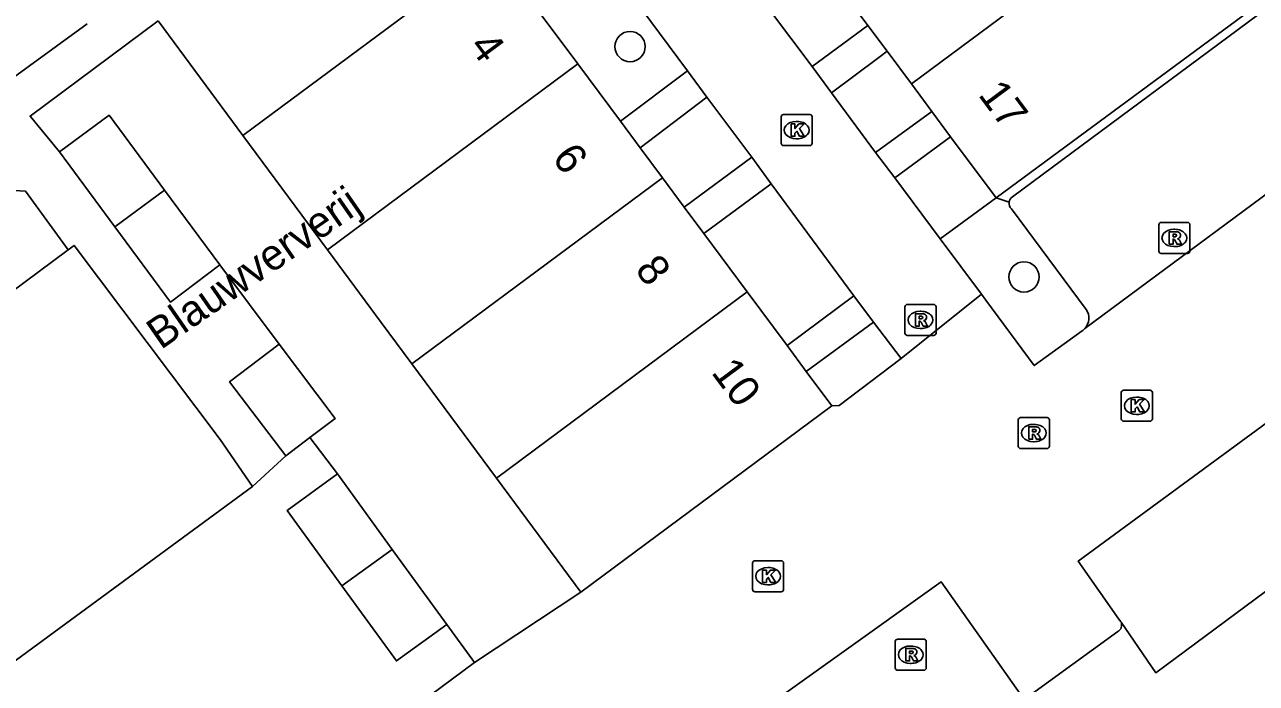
# Model space of a CAD drawing. Extents: x 161801 to 162379, y 382315 to 382832.
# Drawn here: x 162031.71 to 162071.44, y 382446.1 to 382467.36 of the extents above; entities that cross this region are included whole.
import ezdxf

# ---------------------------------------------------------------- set-up
doc = ezdxf.new("R2010")
doc.units = 0
for name, color, linetype in [('IMGEO_Boom', 7, 'Continuous'), ('IMGEO_Erf', 7, 'Continuous'), ('IMGEO_Groenvoorziening', 7, 'Continuous'), ('IMGEO_Kolk', 7, 'Continuous'), ('IMGEO_Openbare_ruimte_label', 7, 'Continuous'), ('IMGEO_Pand', 7, 'Continuous'), ('IMGEO_Pand_nummerreeks', 7, 'Continuous'), ('IMGEO_Parkeervlak_halfverhard', 7, 'Continuous'), ('IMGEO_Parkeervlak_open', 7, 'Continuous'), ('IMGEO_Rijbaan_lokaal_open', 7, 'Continuous'), ('IMGEO_Rioolput', 7, 'Continuous'), ('IMGEO_Voetpad_open', 7, 'Continuous')]:
    doc.layers.add(name, color=color, linetype=linetype)

msp = doc.modelspace()

# ---------------------------------------------------------------- linework, layer by layer
at = {"layer": 'IMGEO_Boom'}
for centre in [(162051.24, 382466.65), (162063.944, 382459.218)]:
    msp.add_circle(centre, 0.489, dxfattribs=at)
at = {"layer": 'IMGEO_Erf'}
for points in [[(162040.915, 382454.037), (162041.8, 382452.86)], [(162045.33, 382447.999), (162046.218, 382446.777)]]:
    msp.add_lwpolyline(points, dxfattribs=at)
at = {"layer": 'IMGEO_Groenvoorziening'}
for points in [[(162063.042, 382461.773), (162061.246, 382460.443)], [(162063.042, 382461.773), (162063.468, 382461.63)]]:
    msp.add_lwpolyline(points, dxfattribs=at)
at = {"layer": 'IMGEO_Kolk'}
for p, q in [((162056.187, 382464.456), (162057.039, 382464.456)), ((162056.112, 382463.53), (162056.112, 382464.382)), ((162056.6, 382464.236), (162056.625, 382464.236)), ((162057.113, 382464.382), (162057.113, 382463.53)), ((162056.623, 382463.676), (162056.598, 382463.676)), ((162057.039, 382463.456), (162056.187, 382463.456)), ((162067.083, 382454.636), (162067.083, 382455.488)), ((162067.158, 382455.562), (162068.01, 382455.562)), ((162067.571, 382455.342), (162067.596, 382455.342)), ((162068.084, 382455.488), (162068.084, 382454.636)), ((162068.01, 382454.562), (162067.158, 382454.562)), ((162067.594, 382454.782), (162067.569, 382454.782)), ((162055.191, 382449.136), (162055.191, 382449.988)), ((162055.266, 382450.062), (162056.118, 382450.062)), ((162055.679, 382449.842), (162055.704, 382449.842)), ((162056.192, 382449.988), (162056.192, 382449.136)), ((162056.118, 382449.062), (162055.266, 382449.062)), ((162055.702, 382449.282), (162055.677, 382449.282))]:
    msp.add_line(p, q, dxfattribs=at)
for points in [[(162056.187, 382464.456), (162057.039, 382464.456)], [(162056.112, 382463.53), (162056.112, 382464.382)], [(162056.433, 382464.156), (162056.556, 382464.156), (162056.556, 382464.005), (162056.686, 382464.156), (162056.85, 382464.156), (162056.704, 382464.005), (162056.857, 382463.756), (162056.705, 382463.756), (162056.62, 382463.92), (162056.556, 382463.853), (162056.556, 382463.756), (162056.433, 382463.756), (162056.433, 382464.156)], [(162057.113, 382464.382), (162057.113, 382463.53)], [(162057.039, 382463.456), (162056.187, 382463.456)], [(162067.083, 382454.636), (162067.083, 382455.488)], [(162067.158, 382455.562), (162068.01, 382455.562)], [(162068.084, 382455.488), (162068.084, 382454.636)], [(162067.404, 382455.262), (162067.527, 382455.262), (162067.527, 382455.111), (162067.657, 382455.262), (162067.821, 382455.262), (162067.675, 382455.111), (162067.828, 382454.862), (162067.676, 382454.862), (162067.591, 382455.026), (162067.527, 382454.959), (162067.527, 382454.862), (162067.404, 382454.862), (162067.404, 382455.262)], [(162068.01, 382454.562), (162067.158, 382454.562)], [(162055.191, 382449.136), (162055.191, 382449.988)], [(162055.266, 382450.062), (162056.118, 382450.062)], [(162055.512, 382449.762), (162055.635, 382449.762), (162055.635, 382449.611), (162055.765, 382449.762), (162055.929, 382449.762), (162055.783, 382449.611), (162055.936, 382449.362), (162055.784, 382449.362), (162055.699, 382449.526), (162055.635, 382449.459), (162055.635, 382449.362), (162055.512, 382449.362), (162055.512, 382449.762)], [(162056.192, 382449.988), (162056.192, 382449.136)], [(162056.118, 382449.062), (162055.266, 382449.062)]]:
    msp.add_lwpolyline(points, dxfattribs=at)
for centre, start, end in [((162056.189, 382464.38), 91.552, 178.448), ((162056.189, 382464.38), 91.552, 178.448), ((162057.037, 382464.38), 1.552, 88.448), ((162057.037, 382464.38), 1.552, 88.448), ((162056.189, 382463.532), 181.552, 268.448), ((162056.189, 382463.532), 181.552, 268.448), ((162057.037, 382463.532), 271.552, 358.448), ((162057.037, 382463.532), 271.552, 358.448), ((162067.16, 382455.486), 91.552, 178.448), ((162067.16, 382455.486), 91.552, 178.448), ((162068.008, 382455.486), 1.552, 88.448), ((162068.008, 382455.486), 1.552, 88.448), ((162067.16, 382454.638), 181.552, 268.448), ((162067.16, 382454.638), 181.552, 268.448), ((162068.008, 382454.638), 271.552, 358.448), ((162068.008, 382454.638), 271.552, 358.448), ((162055.268, 382449.986), 91.552, 178.448), ((162055.268, 382449.986), 91.552, 178.448), ((162056.116, 382449.986), 1.552, 88.448), ((162056.116, 382449.986), 1.552, 88.448), ((162055.268, 382449.138), 181.552, 268.448), ((162055.268, 382449.138), 181.552, 268.448), ((162056.116, 382449.138), 271.552, 358.448), ((162056.116, 382449.138), 271.552, 358.448)]:
    msp.add_arc(centre, 0.0765, start, end, dxfattribs=at)
for centre, major_axis, ratio, start_param, end_param in [((162056.599, 382463.956), (-0.387, 0.002), 0.722429, 4.712389, 7.853982), ((162056.624, 382463.956), (-0.39, 0.002), 0.717154, 1.570796, 4.712389), ((162067.57, 382455.062), (-0.387, 0.002), 0.722429, 4.712389, 7.853982), ((162067.595, 382455.062), (-0.39, 0.002), 0.717154, 1.570796, 4.712389), ((162055.678, 382449.562), (-0.387, 0.002), 0.722429, 4.712389, 7.853982), ((162055.703, 382449.562), (-0.39, 0.002), 0.717154, 1.570796, 4.712389)]:
    msp.add_ellipse(centre, major_axis=major_axis, ratio=ratio, start_param=start_param, end_param=end_param, dxfattribs=at)
at = {"layer": 'IMGEO_Pand'}
for points in [[(162068.51, 382471.53), (162060.316, 382465.444)], [(162068.51, 382471.53), (162071.252, 382467.829), (162063.042, 382461.773)], [(162038.752, 382463.783), (162046.817, 382469.774)], [(162058.911, 382467.335), (162057.589, 382469.115)], [(162048.277, 382467.808), (162049.55, 382466.094)], [(162038.752, 382463.783), (162036.02, 382467.479)], [(162059.529, 382466.503), (162058.911, 382467.335)], [(162060.316, 382465.444), (162059.529, 382466.503)], [(162041.477, 382460.097), (162049.55, 382466.094)], [(162049.55, 382466.094), (162050.926, 382464.243)], [(162060.972, 382464.56), (162060.316, 382465.444)], [(162032.833, 382463.25), (162034.439, 382464.437), (162036.226, 382462.021)], [(162061.579, 382463.743), (162060.972, 382464.56)], [(162050.926, 382464.243), (162051.568, 382463.379)], [(162041.477, 382460.097), (162038.752, 382463.783)], [(162061.579, 382463.743), (162063.042, 382461.773)], [(162032.833, 382463.25), (162034.62, 382460.833)], [(162051.568, 382463.379), (162052.284, 382462.415)], [(162034.62, 382460.833), (162036.226, 382462.021)], [(162036.226, 382462.021), (162038.012, 382459.604)], [(162052.284, 382462.415), (162044.202, 382456.411)], [(162052.284, 382462.415), (162052.988, 382461.467)], [(162052.988, 382461.467), (162053.614, 382460.624)], [(162034.62, 382460.833), (162036.42, 382458.399), (162038.012, 382459.604)], [(162053.614, 382460.624), (162055.017, 382458.735)], [(162028.864, 382456.929), (162033.12, 382460.093)], [(162033.12, 382460.093), (162033.309, 382460.233), (162038.02, 382453.975), (162039.058, 382452.455)], [(162044.202, 382456.411), (162043.211, 382457.751), (162041.477, 382460.097)], [(162055.017, 382458.735), (162046.927, 382452.724)], [(162055.017, 382458.735), (162056.305, 382457.001)], [(162039.918, 382457.045), (162038.324, 382455.838), (162040.133, 382453.445)], [(162039.918, 382457.045), (162041.729, 382454.653), (162040.915, 382454.037)], [(162056.305, 382457.001), (162056.921, 382456.172)], [(162046.927, 382452.724), (162044.202, 382456.411)], [(162056.921, 382456.172), (162057.751, 382455.055)], [(162049.647, 382449.044), (162057.751, 382455.055)], [(162040.133, 382453.445), (162040.915, 382454.037)], [(162041.8, 382452.86), (162040.181, 382451.685), (162041.946, 382449.254)], [(162041.8, 382452.86), (162043.565, 382450.429)], [(162046.927, 382452.724), (162049.647, 382449.044)], [(162039.058, 382452.455), (162020.713, 382438.983), (162019.568, 382440.542)], [(162041.946, 382449.254), (162043.565, 382450.429)], [(162043.565, 382450.429), (162045.33, 382447.999)], [(162041.946, 382449.254), (162043.706, 382446.831), (162045.33, 382447.999)]]:
    msp.add_lwpolyline(points, dxfattribs=at)
at = {"layer": 'IMGEO_Parkeervlak_halfverhard'}
msp.add_lwpolyline([(162072.121, 382454.773), (162074.6, 382451.197), (162068.196, 382446.446), (162067.074, 382448.077)], dxfattribs=at)
at = {"layer": 'IMGEO_Parkeervlak_open'}
for points in [[(162063.569, 382461.806), (162075.931, 382470.972)], [(162063.537, 382461.412), (162065.949, 382458.172)]]:
    msp.add_lwpolyline(points, dxfattribs=at)
for centre, radius, start, end in [((162063.732, 382461.594), 0.266, 172.1568, 222.9698), ((162063.731, 382461.596), 0.265, 127.6785, 172.6216), ((162065.542, 382457.889), 0.495, 317.2389, 34.8135)]:
    msp.add_arc(centre, radius, start, end, dxfattribs=at)
at = {"layer": 'IMGEO_Rijbaan_lokaal_open'}
for points in [[(162065.906, 382457.553), (162079.043, 382467.284)], [(162062.57, 382458.658), (162059.982, 382456.586)], [(162065.818, 382457.478), (162064.275, 382456.359), (162062.709, 382458.471), (162062.57, 382458.658)], [(162057.751, 382455.055), (162057.986, 382455.074), (162059.982, 382456.586)], [(162072.121, 382454.773), (162065.693, 382450.051), (162066.998, 382448.171)], [(162063.951, 382445.581), (162061.27, 382449.381), (162044.277, 382437.229), (162028.301, 382425.803), (162028.36, 382425.699)], [(162046.218, 382446.777), (162049.647, 382449.044)], [(162066.969, 382447.775), (162063.951, 382445.581)], [(162046.218, 382446.777), (162042.301, 382443.865)]]:
    msp.add_lwpolyline(points, dxfattribs=at)
for centre, radius, start, end in [((162065.524, 382457.912), 0.524, 304.1036, 316.7765), ((162066.857, 382447.979), 0.238, 24.2312, 53.6806), ((162066.861, 382447.982), 0.233, 297.5012, 24.1555)]:
    msp.add_arc(centre, radius, start, end, dxfattribs=at)
at = {"layer": 'IMGEO_Rioolput'}
for p, q in [((162068.294, 382460.049), (162068.294, 382460.901)), ((162068.369, 382460.975), (162069.221, 382460.975)), ((162069.295, 382460.901), (162069.295, 382460.049)), ((162068.782, 382460.755), (162068.807, 382460.755)), ((162068.805, 382460.195), (162068.78, 382460.195)), ((162069.221, 382459.975), (162068.369, 382459.975)), ((162060.106, 382457.405), (162060.106, 382458.257)), ((162060.181, 382458.331), (162061.033, 382458.331)), ((162060.594, 382458.111), (162060.619, 382458.111)), ((162061.107, 382458.257), (162061.107, 382457.405)), ((162061.033, 382457.331), (162060.181, 382457.331)), ((162060.617, 382457.551), (162060.592, 382457.551)), ((162063.761, 382453.756), (162063.761, 382454.608)), ((162063.836, 382454.682), (162064.688, 382454.682)), ((162064.762, 382454.608), (162064.762, 382453.756)), ((162064.249, 382454.462), (162064.274, 382454.462)), ((162064.688, 382453.682), (162063.836, 382453.682)), ((162064.272, 382453.902), (162064.247, 382453.902)), ((162059.793, 382446.604), (162059.793, 382447.456)), ((162059.868, 382447.53), (162060.72, 382447.53)), ((162060.794, 382447.456), (162060.794, 382446.604)), ((162060.281, 382447.31), (162060.306, 382447.31)), ((162060.72, 382446.53), (162059.868, 382446.53)), ((162060.304, 382446.75), (162060.279, 382446.75))]:
    msp.add_line(p, q, dxfattribs=at)
for points in [[(162068.294, 382460.049), (162068.294, 382460.901)], [(162068.369, 382460.975), (162069.221, 382460.975)], [(162069.295, 382460.901), (162069.295, 382460.049)], [(162068.883, 382460.673), (162068.631, 382460.675), (162068.631, 382460.275)], [(162068.631, 382460.275), (162068.755, 382460.275), (162068.755, 382460.437), (162068.766, 382460.437)], [(162068.809, 382460.594), (162068.755, 382460.594), (162068.755, 382460.513)], [(162068.755, 382460.513), (162068.807, 382460.513)], [(162068.813, 382460.408), (162068.884, 382460.275), (162069.024, 382460.275), (162068.959, 382460.401)], [(162069.221, 382459.975), (162068.369, 382459.975)], [(162060.106, 382457.405), (162060.106, 382458.257)], [(162060.181, 382458.331), (162061.033, 382458.331)], [(162061.107, 382458.257), (162061.107, 382457.405)], [(162060.695, 382458.029), (162060.443, 382458.031), (162060.443, 382457.631)], [(162060.443, 382457.631), (162060.567, 382457.631), (162060.567, 382457.793), (162060.578, 382457.793)], [(162060.621, 382457.95), (162060.567, 382457.95), (162060.567, 382457.869)], [(162060.567, 382457.869), (162060.619, 382457.869)], [(162060.625, 382457.764), (162060.696, 382457.631), (162060.836, 382457.631), (162060.771, 382457.757)], [(162061.033, 382457.331), (162060.181, 382457.331)], [(162063.761, 382453.756), (162063.761, 382454.608)], [(162063.836, 382454.682), (162064.688, 382454.682)], [(162064.762, 382454.608), (162064.762, 382453.756)], [(162064.35, 382454.38), (162064.098, 382454.382), (162064.098, 382453.982)], [(162064.098, 382453.982), (162064.222, 382453.982), (162064.222, 382454.144), (162064.233, 382454.144)], [(162064.276, 382454.301), (162064.222, 382454.301), (162064.222, 382454.22)], [(162064.222, 382454.22), (162064.274, 382454.22)], [(162064.28, 382454.115), (162064.351, 382453.982), (162064.491, 382453.982), (162064.426, 382454.108)], [(162064.688, 382453.682), (162063.836, 382453.682)], [(162059.793, 382446.604), (162059.793, 382447.456)], [(162059.868, 382447.53), (162060.72, 382447.53)], [(162060.794, 382447.456), (162060.794, 382446.604)], [(162060.382, 382447.228), (162060.13, 382447.23), (162060.13, 382446.83)], [(162060.13, 382446.83), (162060.254, 382446.83), (162060.254, 382446.992), (162060.265, 382446.992)], [(162060.308, 382447.149), (162060.254, 382447.149), (162060.254, 382447.068)], [(162060.254, 382447.068), (162060.306, 382447.068)], [(162060.312, 382446.963), (162060.383, 382446.83), (162060.523, 382446.83), (162060.458, 382446.956)], [(162060.72, 382446.53), (162059.868, 382446.53)]]:
    msp.add_lwpolyline(points, dxfattribs=at)
for centre, radius, start, end in [((162068.371, 382460.899), 0.0765, 91.552, 178.448), ((162068.371, 382460.899), 0.0765, 91.552, 178.448), ((162069.219, 382460.899), 0.0765, 1.552, 88.448), ((162069.219, 382460.899), 0.0765, 1.552, 88.448), ((162068.765, 382460.384), 0.0533, 26.0293, 88.6989), ((162068.791, 382460.702), 0.19, 274.7715, 282.9687), ((162068.815, 382460.498), 0.0964, 77.0061, 93.1865), ((162068.829, 382460.555), 0.0378, 276.6634, 79.6772), ((162068.882, 382460.563), 0.109, 350.3612, 89.416), ((162068.88, 382460.563), 0.112, 277.5842, 350.9817), ((162068.864, 382460.348), 0.108, 29.5134, 73.7905), ((162068.371, 382460.051), 0.0765, 181.552, 268.448), ((162068.371, 382460.051), 0.0765, 181.552, 268.448), ((162069.219, 382460.051), 0.0765, 271.552, 358.448), ((162069.219, 382460.051), 0.0765, 271.552, 358.448), ((162060.183, 382458.255), 0.0765, 91.552, 178.448), ((162060.183, 382458.255), 0.0765, 91.552, 178.448), ((162061.031, 382458.255), 0.0765, 1.552, 88.448), ((162061.031, 382458.255), 0.0765, 1.552, 88.448), ((162060.577, 382457.74), 0.0533, 26.0293, 88.6989), ((162060.603, 382458.058), 0.19, 274.7715, 282.9687), ((162060.627, 382457.854), 0.0964, 77.0061, 93.1865), ((162060.641, 382457.911), 0.0378, 276.6634, 79.6772), ((162060.694, 382457.919), 0.109, 350.3612, 89.416), ((162060.692, 382457.919), 0.112, 277.5842, 350.9817), ((162060.676, 382457.704), 0.108, 29.5134, 73.7905), ((162060.183, 382457.407), 0.0765, 181.552, 268.448), ((162060.183, 382457.407), 0.0765, 181.552, 268.448), ((162061.031, 382457.407), 0.0765, 271.552, 358.448), ((162061.031, 382457.407), 0.0765, 271.552, 358.448), ((162063.838, 382454.606), 0.0765, 91.552, 178.448), ((162063.838, 382454.606), 0.0765, 91.552, 178.448), ((162064.686, 382454.606), 0.0765, 1.552, 88.448), ((162064.686, 382454.606), 0.0765, 1.552, 88.448), ((162064.232, 382454.091), 0.0533, 26.0293, 88.6989), ((162064.258, 382454.409), 0.19, 274.7715, 282.9687), ((162064.282, 382454.205), 0.0964, 77.0061, 93.1865), ((162064.296, 382454.262), 0.0378, 276.6634, 79.6772), ((162064.349, 382454.27), 0.109, 350.3612, 89.416), ((162064.347, 382454.27), 0.112, 277.5842, 350.9817), ((162064.331, 382454.055), 0.108, 29.5134, 73.7905), ((162063.838, 382453.758), 0.0765, 181.552, 268.448), ((162063.838, 382453.758), 0.0765, 181.552, 268.448), ((162064.686, 382453.758), 0.0765, 271.552, 358.448), ((162064.686, 382453.758), 0.0765, 271.552, 358.448), ((162059.87, 382447.454), 0.0765, 91.552, 178.448), ((162059.87, 382447.454), 0.0765, 91.552, 178.448), ((162060.718, 382447.454), 0.0765, 1.552, 88.448), ((162060.718, 382447.454), 0.0765, 1.552, 88.448), ((162060.264, 382446.939), 0.0533, 26.0293, 88.6989), ((162060.29, 382447.257), 0.19, 274.7715, 282.9687), ((162060.314, 382447.053), 0.0964, 77.0061, 93.1865), ((162060.328, 382447.11), 0.0378, 276.6634, 79.6772), ((162060.381, 382447.118), 0.109, 350.3612, 89.416), ((162060.379, 382447.118), 0.112, 277.5842, 350.9817), ((162060.363, 382446.903), 0.108, 29.5134, 73.7905), ((162059.87, 382446.606), 0.0765, 181.552, 268.448), ((162059.87, 382446.606), 0.0765, 181.552, 268.448), ((162060.718, 382446.606), 0.0765, 271.552, 358.448), ((162060.718, 382446.606), 0.0765, 271.552, 358.448)]:
    msp.add_arc(centre, radius, start, end, dxfattribs=at)
for centre, major_axis, ratio, start_param, end_param in [((162068.781, 382460.475), (-0.387, 0.002), 0.722429, 4.712389, 7.853982), ((162068.806, 382460.475), (-0.39, 0.002), 0.717154, 1.570796, 4.712389), ((162060.593, 382457.831), (-0.387, 0.002), 0.722429, 4.712389, 7.853982), ((162060.618, 382457.831), (-0.39, 0.002), 0.717154, 1.570796, 4.712389), ((162064.248, 382454.182), (-0.387, 0.002), 0.722429, 4.712389, 7.853982), ((162064.273, 382454.182), (-0.39, 0.002), 0.717154, 1.570796, 4.712389), ((162060.28, 382447.03), (-0.387, 0.002), 0.722429, 4.712389, 7.853982), ((162060.305, 382447.03), (-0.39, 0.002), 0.717154, 1.570796, 4.712389)]:
    msp.add_ellipse(centre, major_axis=major_axis, ratio=ratio, start_param=start_param, end_param=end_param, dxfattribs=at)
at = {"layer": 'IMGEO_Voetpad_open'}
for points in [[(162054.397, 382469.637), (162057.108, 382466.011)], [(162053.095, 382465.869), (162050.42, 382469.484)], [(162021.844, 382467.777), (162023.567, 382465.307), (162024.49, 382465.967), (162025.798, 382464.194), (162029.013, 382463.958), (162033.734, 382467.382)], [(162036.02, 382467.479), (162031.888, 382464.407), (162032.833, 382463.25)], [(162058.911, 382467.335), (162057.108, 382466.011)], [(162057.732, 382465.153), (162059.258, 382466.299), (162059.529, 382466.503)], [(162057.108, 382466.011), (162057.732, 382465.153)], [(162053.095, 382465.869), (162050.926, 382464.243)], [(162053.712, 382465.013), (162053.095, 382465.869)], [(162051.568, 382463.379), (162053.712, 382465.013)], [(162055.167, 382463.079), (162053.712, 382465.013)], [(162057.732, 382465.153), (162059.159, 382463.236)], [(162060.972, 382464.56), (162059.159, 382463.236)], [(162059.784, 382462.415), (162061.579, 382463.743)], [(162059.159, 382463.236), (162059.784, 382462.415)], [(162055.167, 382463.079), (162052.988, 382461.467)], [(162055.793, 382462.225), (162055.167, 382463.079)], [(162033.12, 382460.093), (162031.744, 382461.98), (162027.597, 382462.232), (162027.134, 382461.905), (162025.891, 382460.987)], [(162053.614, 382460.624), (162055.793, 382462.225)], [(162058.455, 382458.611), (162055.793, 382462.225)], [(162061.246, 382460.443), (162059.784, 382462.415)], [(162062.57, 382458.658), (162061.246, 382460.443)], [(162038.012, 382459.604), (162039.918, 382457.045)], [(162058.455, 382458.611), (162056.305, 382457.001)], [(162059.092, 382457.759), (162058.455, 382458.611)], [(162056.921, 382456.172), (162059.092, 382457.759)], [(162059.982, 382456.586), (162059.092, 382457.759)], [(162039.058, 382452.455), (162040.133, 382453.445)]]:
    msp.add_lwpolyline(points, dxfattribs=at)

# ---------------------------------------------------------------- texts
at = {"layer": 'IMGEO_Openbare_ruimte_label'}
msp.add_text('Blauwververij', height=1, rotation=34.6915, dxfattribs=at).set_placement((162036.104, 382456.853))
at = {"layer": 'IMGEO_Pand_nummerreeks'}
for s, rotation, p in [('4', 306.6061, (162046.021, 382466.652)), ('17', 306.6003, (162062.445, 382465.093)), ('6', 306.6061, (162048.696, 382463.052)), ('8', 306.6061, (162051.373, 382459.448)), ('10', 306.6061, (162053.835, 382456.135))]:
    msp.add_text(s, height=1, rotation=rotation, dxfattribs=at).set_placement(p)

doc.saveas('drawing.dxf')
